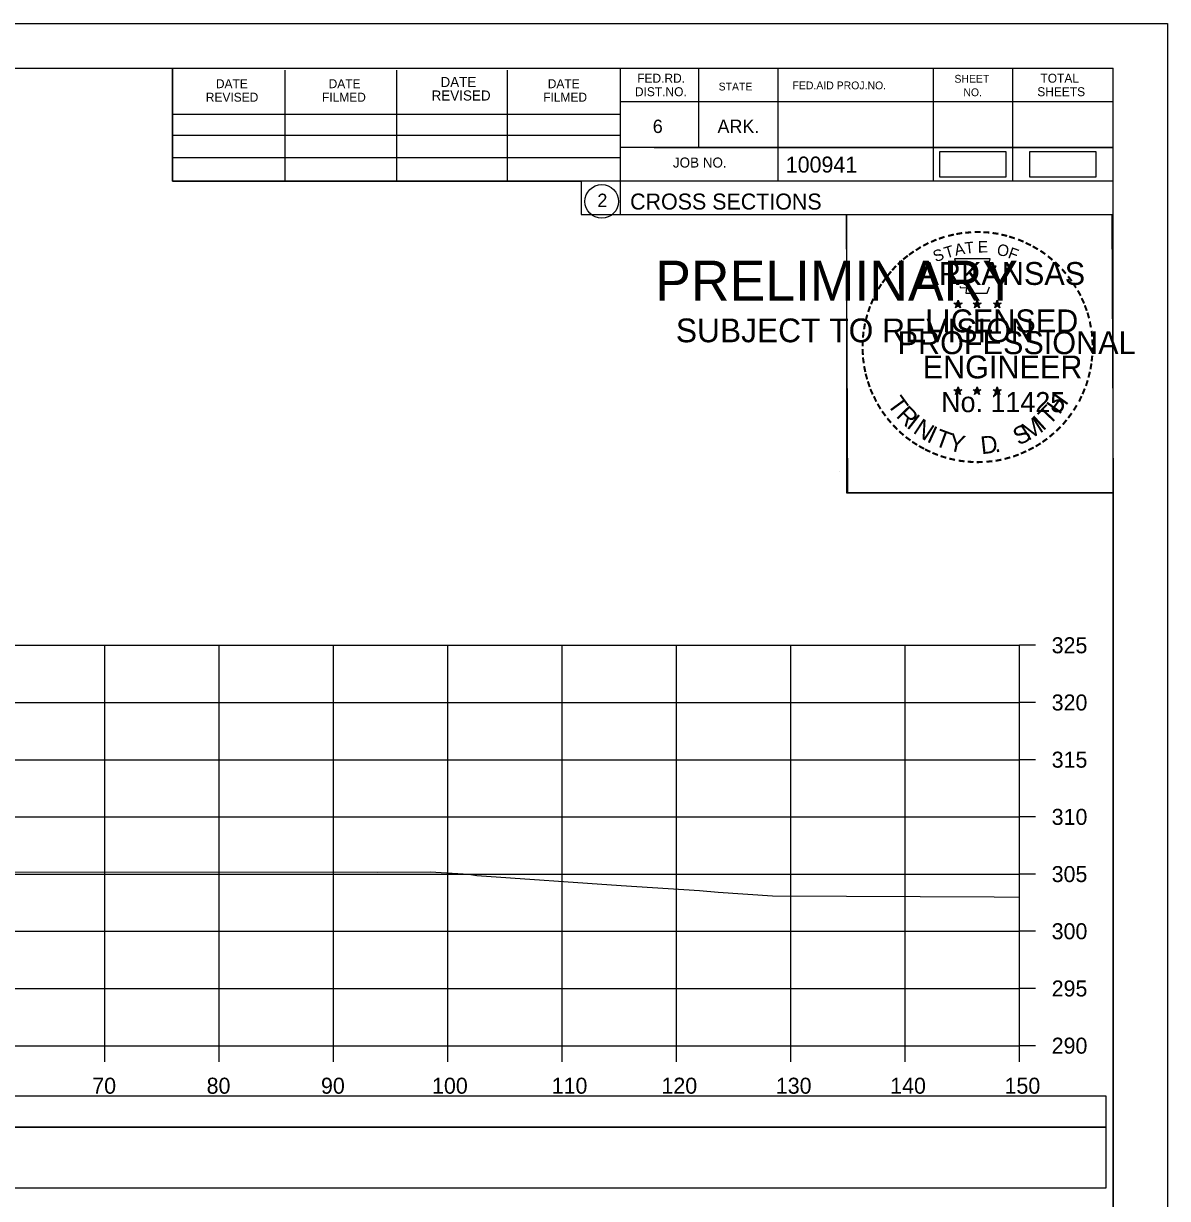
# Model space of a CAD drawing. Extents: x 1370538 to 1372872, y 376220 to 381127.
# Drawn here: x 1372771.5 to 1372871.6, y 378159.8 to 378262.5 of the extents above; entities that cross this region are included whole.
import ezdxf

# ---------------------------------------------------------------- set-up
doc = ezdxf.new("R2010")
doc.units = 0
for name, color, linetype in [('Default', 7, 'Continuous'), ('R_Border Notes', 7, 'Continuous'), ('R_Border PE', 7, 'Continuous'), ('R_Border Prem', 7, 'Continuous'), ('R_Dimension', 7, 'Continuous'), ('R_Grid', 7, 'Continuous'), ('R_Horz Alg Annot', 7, 'Continuous'), ('R_No Plot', 7, 'Continuous'), ('T_Indications', 7, 'Continuous'), ('T_Notes', 7, 'Continuous')]:
    doc.layers.add(name, color=color, linetype=linetype)

msp = doc.modelspace()

# ---------------------------------------------------------------- linework, layer by layer
at = {"layer": 'Default'}
for points in [[(1372851.64, 378249.15), (1372857.47, 378249.15), (1372857.47, 378251.33), (1372851.64, 378251.33)], [(1372859.51, 378249.15), (1372865.34, 378249.15), (1372865.34, 378251.33), (1372859.51, 378251.33)]]:
    msp.add_lwpolyline(points, close=True, dxfattribs=at)
at = {"layer": 'R_Border Notes'}
for p, q in [((1372550.65, 378258.65), (1372866.83, 378258.65)), ((1372784.57, 378248.77), (1372784.57, 378258.65)), ((1372794.43, 378248.77), (1372794.43, 378258.45)), ((1372804.19, 378248.77), (1372804.19, 378258.45)), ((1372813.87, 378248.77), (1372813.87, 378258.45)), ((1372823.73, 378258.65), (1372823.73, 378245.85)), ((1372830.57, 378258.65), (1372830.57, 378251.71)), ((1372837.51, 378258.65), (1372837.51, 378248.77)), ((1372851.09, 378258.65), (1372851.09, 378248.77)), ((1372858.03, 378258.65), (1372858.03, 378248.77)), ((1372866.83, 378053.19), (1372866.83, 378258.65)), ((1372866.83, 378255.71), (1372823.73, 378255.71)), ((1372866.83, 378255.73), (1372866.83, 378255.73)), ((1372784.57, 378254.63), (1372823.73, 378254.63)), ((1372784.57, 378252.77), (1372823.73, 378252.77)), ((1372866.83, 378251.71), (1372823.73, 378251.71)), ((1372826.69, 378251.71), (1372866.83, 378251.71)), ((1372784.57, 378248.77), (1372784.57, 378250.83)), ((1372784.57, 378250.83), (1372823.73, 378250.83)), ((1372866.83, 378248.77), (1372784.57, 378248.77)), ((1372823.73, 378245.85), (1372866.83, 378245.85))]:
    msp.add_line(p, q, dxfattribs=at)
msp.add_circle((1372822.11, 378246.99), 1.47, dxfattribs=at)
at = {"layer": 'R_Border Prem'}
for p, q in [((1372858.65, 378173.19), (1372858.65, 378208.19)), ((1372860.05, 378208.19), (1372858.65, 378208.19)), ((1372860.05, 378203.19), (1372858.65, 378203.19)), ((1372860.05, 378198.19), (1372858.65, 378198.19)), ((1372860.05, 378193.19), (1372858.65, 378193.19)), ((1372860.05, 378188.19), (1372858.65, 378188.19)), ((1372860.05, 378183.19), (1372858.65, 378183.19)), ((1372860.05, 378178.19), (1372858.65, 378178.19)), ((1372558.65, 378173.19), (1372858.65, 378173.19)), ((1372778.65, 378171.79), (1372778.65, 378173.19)), ((1372788.65, 378171.79), (1372788.65, 378173.19)), ((1372798.65, 378171.79), (1372798.65, 378173.19)), ((1372808.65, 378171.79), (1372808.65, 378173.19)), ((1372818.65, 378171.79), (1372818.65, 378173.19)), ((1372828.65, 378171.79), (1372828.65, 378173.19)), ((1372838.65, 378171.79), (1372838.65, 378173.19)), ((1372848.65, 378171.79), (1372848.65, 378173.19)), ((1372858.65, 378171.79), (1372858.65, 378173.19)), ((1372860.05, 378173.19), (1372858.65, 378173.19))]:
    msp.add_line(p, q, dxfattribs=at)
at = {"layer": 'R_Dimension'}
msp.add_lwpolyline([(1372755.15, 378188.38), (1372802.54, 378188.37), (1372807.11, 378188.4), (1372810.49, 378188.17), (1372811.19, 378188.07), (1372823.8, 378187.2), (1372830.66, 378186.74), (1372832.3, 378186.6), (1372837.04, 378186.3), (1372856.43, 378186.2), (1372858.65, 378186.18)], dxfattribs=at)
at = {"layer": 'R_Grid'}
for p, q in [((1372558.65, 378208.19), (1372858.65, 378208.19)), ((1372778.65, 378173.19), (1372778.65, 378208.19)), ((1372788.65, 378173.19), (1372788.65, 378208.19)), ((1372798.65, 378173.19), (1372798.65, 378208.19)), ((1372808.65, 378173.19), (1372808.65, 378208.19)), ((1372818.65, 378173.19), (1372818.65, 378208.19)), ((1372828.65, 378173.19), (1372828.65, 378208.19)), ((1372838.65, 378173.19), (1372838.65, 378208.19)), ((1372848.65, 378173.19), (1372848.65, 378208.19)), ((1372858.65, 378173.19), (1372858.65, 378208.19)), ((1372558.65, 378203.19), (1372858.65, 378203.19)), ((1372558.65, 378198.19), (1372858.65, 378198.19)), ((1372558.65, 378193.19), (1372858.65, 378193.19)), ((1372558.65, 378188.19), (1372858.65, 378188.19)), ((1372558.65, 378183.19), (1372858.65, 378183.19)), ((1372558.65, 378178.19), (1372858.65, 378178.19)), ((1372558.65, 378173.19), (1372858.65, 378173.19))]:
    msp.add_line(p, q, dxfattribs=at)
at = {"layer": 'R_Horz Alg Annot'}
for points in [[(1372551.09, 378166.07), (1372866.22, 378166.07), (1372866.22, 378168.78), (1372551.09, 378168.78)], [(1372551.09, 378160.75), (1372866.22, 378160.75), (1372866.22, 378166.07), (1372551.09, 378166.07)]]:
    msp.add_lwpolyline(points, close=True, dxfattribs=at)
at = {"layer": 'R_No Plot'}
for p, q in [((1372538.25, 378262.54), (1372871.58, 378262.54)), ((1372842.86, 378223.39), (1372842.86, 378223.39))]:
    msp.add_line(p, q, dxfattribs=at)
for points in [[(1372538.24, 378262.54), (1372871.58, 378262.54), (1372871.58, 378049.21), (1372538.24, 378049.21)], [(1372784.57, 378258.65), (1372784.57, 378248.77), (1372820.3, 378248.77), (1372820.3, 378245.85), (1372843.5, 378245.85), (1372843.5, 378221.52), (1372866.83, 378221.52), (1372866.83, 378053.19), (1372550.65, 378053.19), (1372550.65, 378258.65)], [(1372843.5, 378245.85), (1372866.71, 378245.85), (1372866.83, 378221.52), (1372843.62, 378221.52)]]:
    msp.add_lwpolyline(points, close=True, dxfattribs=at)
at = {"layer": 'T_Indications'}
for p, q in [((1372853.26, 378238.36), (1372853.22, 378238.11)), ((1372853.26, 378237.99), (1372853.26, 378238.36)), ((1372853.26, 378238.36), (1372853.31, 378238.11)), ((1372854.93, 378238.36), (1372854.89, 378238.11)), ((1372854.93, 378237.99), (1372854.93, 378238.36)), ((1372854.93, 378238.36), (1372854.98, 378238.11)), ((1372856.69, 378238.35), (1372856.65, 378238.09)), ((1372856.69, 378237.98), (1372856.69, 378238.35)), ((1372856.69, 378238.35), (1372856.74, 378238.1)), ((1372852.91, 378238.1), (1372853.26, 378237.99)), ((1372852.91, 378238.1), (1372853.16, 378238.06)), ((1372852.91, 378238.1), (1372853.15, 378237.98)), ((1372853.04, 378237.7), (1372853.26, 378237.99)), ((1372853.04, 378237.7), (1372853.17, 378237.94)), ((1372853.04, 378237.7), (1372853.26, 378237.91)), ((1372853.61, 378238.1), (1372853.26, 378237.99)), ((1372853.47, 378237.7), (1372853.26, 378237.99)), ((1372853.47, 378237.7), (1372853.26, 378237.91)), ((1372853.61, 378238.1), (1372853.32, 378238.06)), ((1372853.47, 378237.7), (1372853.34, 378237.99)), ((1372853.61, 378238.1), (1372853.4, 378238)), ((1372854.58, 378238.1), (1372854.93, 378237.99)), ((1372854.58, 378238.1), (1372854.83, 378238.06)), ((1372854.58, 378238.1), (1372854.82, 378237.98)), ((1372854.71, 378237.7), (1372854.93, 378237.99)), ((1372854.71, 378237.7), (1372854.84, 378237.94)), ((1372854.71, 378237.7), (1372854.93, 378237.91)), ((1372855.28, 378238.1), (1372854.93, 378237.99)), ((1372855.14, 378237.7), (1372854.93, 378237.99)), ((1372855.14, 378237.7), (1372854.93, 378237.91)), ((1372855.28, 378238.1), (1372854.99, 378238.06)), ((1372855.14, 378237.7), (1372855.01, 378237.99)), ((1372855.28, 378238.1), (1372855.07, 378238)), ((1372856.35, 378238.09), (1372856.69, 378237.98)), ((1372856.35, 378238.09), (1372856.6, 378238.05)), ((1372856.35, 378238.09), (1372856.58, 378237.97)), ((1372856.48, 378237.68), (1372856.69, 378237.98)), ((1372856.48, 378237.68), (1372856.6, 378237.93)), ((1372856.48, 378237.68), (1372856.69, 378237.9)), ((1372857.04, 378238.09), (1372856.69, 378237.98)), ((1372856.91, 378237.68), (1372856.69, 378237.98)), ((1372856.91, 378237.68), (1372856.69, 378237.9)), ((1372857.04, 378238.09), (1372856.76, 378238.04)), ((1372856.91, 378237.68), (1372856.77, 378237.98)), ((1372857.04, 378238.09), (1372856.84, 378237.99)), ((1372852.91, 378230.53), (1372853.26, 378230.42)), ((1372852.91, 378230.53), (1372853.16, 378230.49)), ((1372852.91, 378230.53), (1372853.14, 378230.41)), ((1372853.04, 378230.12), (1372853.26, 378230.42)), ((1372853.04, 378230.12), (1372853.17, 378230.37)), ((1372853.04, 378230.12), (1372853.25, 378230.34)), ((1372853.26, 378230.79), (1372853.22, 378230.53)), ((1372853.47, 378230.12), (1372853.25, 378230.34)), ((1372853.26, 378230.42), (1372853.26, 378230.79)), ((1372853.26, 378230.79), (1372853.31, 378230.54)), ((1372853.6, 378230.53), (1372853.26, 378230.42)), ((1372853.47, 378230.12), (1372853.26, 378230.42)), ((1372853.6, 378230.53), (1372853.32, 378230.48)), ((1372853.47, 378230.12), (1372853.33, 378230.41)), ((1372853.6, 378230.53), (1372853.4, 378230.43)), ((1372854.58, 378230.53), (1372854.93, 378230.42)), ((1372854.58, 378230.53), (1372854.83, 378230.49)), ((1372854.58, 378230.53), (1372854.81, 378230.41)), ((1372854.71, 378230.12), (1372854.93, 378230.42)), ((1372854.71, 378230.12), (1372854.84, 378230.37)), ((1372854.71, 378230.12), (1372854.92, 378230.34)), ((1372854.93, 378230.79), (1372854.88, 378230.53)), ((1372855.14, 378230.12), (1372854.92, 378230.34)), ((1372854.93, 378230.42), (1372854.93, 378230.79)), ((1372854.93, 378230.79), (1372854.97, 378230.54)), ((1372855.27, 378230.53), (1372854.93, 378230.42)), ((1372855.14, 378230.12), (1372854.93, 378230.42)), ((1372855.27, 378230.53), (1372854.99, 378230.48)), ((1372855.14, 378230.12), (1372855, 378230.41)), ((1372855.27, 378230.53), (1372855.07, 378230.43)), ((1372856.34, 378230.52), (1372856.69, 378230.41)), ((1372856.34, 378230.52), (1372856.6, 378230.48)), ((1372856.34, 378230.52), (1372856.58, 378230.4)), ((1372856.48, 378230.11), (1372856.69, 378230.41)), ((1372856.48, 378230.11), (1372856.6, 378230.36)), ((1372856.48, 378230.11), (1372856.69, 378230.33)), ((1372856.69, 378230.78), (1372856.65, 378230.52)), ((1372856.69, 378230.41), (1372856.69, 378230.78)), ((1372856.69, 378230.78), (1372856.74, 378230.53)), ((1372857.04, 378230.52), (1372856.69, 378230.41)), ((1372856.91, 378230.11), (1372856.69, 378230.41)), ((1372856.91, 378230.11), (1372856.69, 378230.33)), ((1372857.04, 378230.52), (1372856.75, 378230.47)), ((1372856.91, 378230.11), (1372856.77, 378230.4)), ((1372857.04, 378230.52), (1372856.84, 378230.42))]:
    msp.add_line(p, q, dxfattribs=at)
for points in [[(1372852.95, 378241.98), (1372853.22, 378241.16)], [(1372856.46, 378241.06), (1372856.61, 378241.34), (1372855.92, 378241.32), (1372856.07, 378241.98), (1372852.95, 378241.98)], [(1372853.44, 378239.56), (1372853.44, 378239.47), (1372854.01, 378239.45), (1372853.95, 378238.98), (1372855.82, 378238.98), (1372856.02, 378239.52)], [(1372853.26, 378238.36), (1372853.47, 378237.7), (1372852.91, 378238.1), (1372853.61, 378238.1), (1372853.04, 378237.7), (1372853.26, 378238.36)], [(1372854.93, 378238.36), (1372855.14, 378237.7), (1372854.58, 378238.1), (1372855.28, 378238.1), (1372854.71, 378237.7), (1372854.93, 378238.36)], [(1372856.69, 378238.35), (1372856.91, 378237.68), (1372856.35, 378238.09), (1372857.04, 378238.09), (1372856.48, 378237.68), (1372856.69, 378238.35)], [(1372853.26, 378230.79), (1372853.47, 378230.12), (1372852.91, 378230.53), (1372853.6, 378230.53), (1372853.04, 378230.12), (1372853.26, 378230.79)], [(1372854.93, 378230.79), (1372855.14, 378230.12), (1372854.58, 378230.53), (1372855.27, 378230.53), (1372854.71, 378230.12), (1372854.93, 378230.79)], [(1372856.69, 378230.78), (1372856.91, 378230.11), (1372856.34, 378230.52), (1372857.04, 378230.52), (1372856.48, 378230.11), (1372856.69, 378230.78)]]:
    msp.add_lwpolyline(points, dxfattribs=at)
for centre, radius in [((1372853.26, 378237.99), 0.172), ((1372853.26, 378237.99), 0.145), ((1372853.26, 378237.99), 0.116), ((1372853.26, 378237.99), 0.0991), ((1372853.26, 378237.99), 0.0747), ((1372853.26, 378237.99), 0.0495), ((1372853.26, 378237.99), 0.0296), ((1372854.93, 378237.99), 0.172), ((1372854.93, 378237.99), 0.145), ((1372854.93, 378237.99), 0.116), ((1372854.93, 378237.99), 0.0991), ((1372854.93, 378237.99), 0.0747), ((1372854.93, 378237.99), 0.0495), ((1372854.93, 378237.99), 0.0296), ((1372856.69, 378237.98), 0.172), ((1372856.69, 378237.98), 0.145), ((1372856.69, 378237.98), 0.116), ((1372856.69, 378237.98), 0.0991), ((1372856.69, 378237.98), 0.0747), ((1372856.69, 378237.98), 0.0495), ((1372856.69, 378237.98), 0.0296), ((1372853.26, 378230.42), 0.172), ((1372853.26, 378230.42), 0.145), ((1372853.26, 378230.42), 0.116), ((1372853.26, 378230.42), 0.0991), ((1372853.26, 378230.42), 0.0747), ((1372853.26, 378230.42), 0.0495), ((1372853.26, 378230.42), 0.0296), ((1372854.92, 378230.42), 0.172), ((1372854.92, 378230.42), 0.145), ((1372854.92, 378230.42), 0.116), ((1372854.92, 378230.42), 0.0991), ((1372854.92, 378230.42), 0.0747), ((1372854.92, 378230.42), 0.0495), ((1372854.92, 378230.42), 0.0296), ((1372856.69, 378230.41), 0.172), ((1372856.69, 378230.41), 0.145), ((1372856.69, 378230.41), 0.116), ((1372856.69, 378230.41), 0.0991), ((1372856.69, 378230.41), 0.0747), ((1372856.69, 378230.41), 0.0495), ((1372856.69, 378230.41), 0.0296)]:
    msp.add_circle(centre, radius, dxfattribs=at)

# ---------------------------------------------------------------- texts
at = {"layer": 'R_Border Notes'}
for s, height, p in [('DATE', 0.879, (1372808.01, 378256.99)), ('FED.RD.', 0.782, (1372825.21, 378257.37)), ('SHEET', 0.684, (1372852.95, 378257.37)), ('TOTAL', 0.782, (1372860.47, 378257.37)), ('DATE', 0.782, (1372788.37, 378256.89)), ('DATE', 0.782, (1372798.23, 378256.89)), ('DATE', 0.782, (1372817.39, 378256.89)), ('DIST.NO.', 0.782, (1372825.01, 378256.19)), ('STATE', 0.684, (1372832.33, 378256.69)), ('FED.AID PROJ.NO.', 0.684, (1372838.79, 378256.79)), ('NO.', 0.684, (1372853.73, 378256.19)), ('SHEETS', 0.782, (1372860.19, 378256.19)), ('REVISED', 0.782, (1372787.49, 378255.71)), ('FILMED', 0.782, (1372797.65, 378255.71)), ('REVISED', 0.879, (1372807.23, 378255.81)), ('FILMED', 0.782, (1372816.99, 378255.71)), ('6', 1.17, (1372826.57, 378252.97)), ('ARK.', 1.172, (1372832.23, 378252.97)), ('JOB NO.', 0.879, (1372828.33, 378249.95)), ('100941', 1.4, (1372838.2, 378249.51)), ('2', 1.17, (1372821.73, 378246.5)), ('CROSS SECTIONS', 1.4, (1372824.59, 378246.28))]:
    msp.add_text(s, height=height, rotation=360, dxfattribs=at).set_placement(p)
at = {"layer": 'R_Border PE'}
for s, p in [('325', (1372861.45, 378207.49)), ('320', (1372861.45, 378202.49)), ('315', (1372861.45, 378197.49)), ('310', (1372861.45, 378192.49)), ('305', (1372861.45, 378187.49)), ('300', (1372861.45, 378182.49)), ('295', (1372861.45, 378177.49)), ('290', (1372861.45, 378172.49)), ('70', (1372777.56, 378168.99)), ('80', (1372787.56, 378168.99)), ('90', (1372797.56, 378168.99)), ('100', (1372807.27, 378168.99)), ('110', (1372817.73, 378168.99)), ('120', (1372827.33, 378168.99)), ('130', (1372837.33, 378168.99)), ('140', (1372847.33, 378168.99)), ('150', (1372857.33, 378168.99))]:
    msp.add_text(s, height=1.4, dxfattribs=at).set_placement(p)
at = {"layer": 'T_Indications'}
for s, height, rotation, p in [('-', 1.6, 24.3072, (1372851.07, 378242.84)), ('-', 1.6, 19.1761, (1372851.7, 378243.11)), ('-', 1.6, 13.6301, (1372852.45, 378243.35)), ('-', 1.6, 10.2193, (1372853.13, 378243.51)), ('T', 1, 6.0228, (1372853.9, 378242.41)), ('-', 1.6, 5.8968, (1372853.86, 378243.62)), ('-', 1.6, 0.1862, (1372854.63, 378243.69)), ('E', 1, 0.8323, (1372855, 378242.52)), ('-', 1.6, 357.743, (1372855.35, 378243.68)), ('-', 1.6, 352.1617, (1372856.1, 378243.63)), ('-', 1.6, 347.2049, (1372856.82, 378243.51)), ('-', 1.6, 342.3362, (1372857.45, 378243.36)), ('-', 1.6, 337.8551, (1372858.19, 378243.13)), ('-', 1.6, 36.2317, (1372849.26, 378241.76)), ('-', 1.6, 34.0636, (1372849.84, 378242.15)), ('-', 1.6, 28.7918, (1372850.43, 378242.52)), ('S', 1, 21.594, (1372851.31, 378241.66)), ('T', 1, 16.4036, (1372852.22, 378241.99)), ('A', 1, 11.2132, (1372853.05, 378242.24)), ('O', 1, 350.4515, (1372856.61, 378242.31)), ('F', 1, 340.0707, (1372857.56, 378242.08)), ('-', 1.6, 334.1211, (1372858.82, 378242.86)), ('-', 1.6, 329.6409, (1372859.4, 378242.58)), ('-', 1.6, 325.8627, (1372860.04, 378242.22)), ('-', 1.6, 42.9622, (1372848.35, 378240.96)), ('-', 1.6, 38.9507, (1372848.78, 378241.38)), ('ARKANSAS', 2, 360, (1372849.81, 378239.69)), ('-', 1.6, 320.5297, (1372860.65, 378241.79)), ('-', 1.6, 315.5786, (1372861.25, 378241.3)), ('-', 1.6, 50.6142, (1372847.5, 378240)), ('-', 1.6, 48.423, (1372847.9, 378240.49)), ('-', 1.6, 309.8797, (1372861.82, 378240.75)), ('-', 1.6, 306.6522, (1372862.34, 378240.15)), ('-', 1.6, 58.0706, (1372846.76, 378238.91)), ('-', 1.6, 54.2325, (1372847.09, 378239.43)), ('-', 1.4, 303.6753, (1372862.83, 378239.58)), ('-', 1.6, 67.7743, (1372846.19, 378237.68)), ('-', 1.6, 62.8713, (1372846.45, 378238.29)), ('-', 1.6, 299.6684, (1372863.15, 378238.98)), ('-', 1.6, 294.6628, (1372863.47, 378238.37)), ('-', 1.6, 72.3945, (1372845.97, 378237.05)), ('LICENSED', 2, 360, (1372850.4, 378235.55)), ('DWB', 0.01, 360, (1372853.25, 378237.99)), ('DWB', 0.01, 360, (1372854.92, 378237.99)), ('DWB', 0.01, 360, (1372856.68, 378237.98)), ('-', 1.6, 290.5728, (1372863.73, 378237.79)), ('-', 1.6, 81.2013, (1372845.64, 378235.62)), ('-', 1.6, 75.461, (1372845.77, 378236.34)), ('-', 1.6, 285.1233, (1372863.96, 378237.21)), ('-', 1.6, 280.5493, (1372864.16, 378236.47)), ('-', 1.6, 85.1863, (1372845.56, 378234.93)), ('PROFESSIONAL', 2, 360, (1372847.98, 378233.64)), ('-', 1.6, 276.5962, (1372864.32, 378235.7)), ('-', 1.6, 89.0622, (1372845.54, 378234.23)), ('-', 1.6, 274.3301, (1372864.38, 378234.98)), ('-', 1.6, 269.9407, (1372864.42, 378234.34)), ('-', 1.6, 94.1959, (1372845.57, 378233.51)), ('-', 1.6, 98.9479, (1372845.65, 378232.84)), ('ENGINEER', 2, 360, (1372850.17, 378231.52)), ('-', 1.6, 263.5172, (1372864.4, 378233.68)), ('-', 1.6, 101.7149, (1372845.78, 378232.11)), ('-', 1.6, 260.9953, (1372864.33, 378233.02)), ('-', 1.6, 105.4578, (1372845.94, 378231.51)), ('-', 1.6, 109.0874, (1372846.16, 378230.88)), ('-', 1.6, 252.8681, (1372864.04, 378231.63)), ('-', 1.6, 255.7626, (1372864.22, 378232.35)), ('-', 1.6, 114.0643, (1372846.41, 378230.28)), ('T', 1.54, 306.0406, (1372847.02, 378229.26)), ('No. 11425', 1.757, 360, (1372851.79, 378228.57)), ('DWB', 0.01, 360, (1372853.24, 378230.42)), ('DWB', 0.01, 360, (1372854.91, 378230.42)), ('DWB', 0.01, 360, (1372856.68, 378230.41)), ('H', 1.54, 54.6088, (1372862.14, 378228.29)), ('-', 1.6, 247.8887, (1372863.81, 378230.95)), ('-', 1.6, 115.7289, (1372846.72, 378229.67)), ('-', 1.6, 120.4471, (1372847.07, 378229.08)), ('R', 1.54, 314.005, (1372847.78, 378228.21)), ('T', 1.54, 46.6444, (1372861.25, 378227.35)), ('-', 1.6, 239.0712, (1372863.16, 378229.57)), ('-', 1.6, 244.6197, (1372863.55, 378230.32)), ('-', 1.6, 125.8934, (1372847.48, 378228.52)), ('-', 1.6, 130.7181, (1372847.94, 378227.97)), ('I', 1.54, 321.9694, (1372848.68, 378227.28)), ('M', 1.54, 32.6563, (1372859.4, 378226.03)), ('I', 1.54, 42.1136, (1372860.68, 378226.87)), ('-', 1.6, 233.8452, (1372862.76, 378228.92)), ('-', 1.6, 134.2238, (1372848.46, 378227.42)), ('N', 1.54, 326.5002, (1372849.25, 378226.81)), ('I', 1.54, 335.3603, (1372850.45, 378226.02)), ('T', 1.54, 339.8912, (1372851.12, 378225.69)), ('S', 1.54, 26.9312, (1372858.56, 378225.62)), ('-', 1.6, 225.7653, (1372861.85, 378227.79)), ('-', 1.6, 231.2538, (1372862.33, 378228.35)), ('-', 1.6, 138.9338, (1372848.98, 378226.96)), ('-', 1.6, 144.6463, (1372849.54, 378226.55)), ('-', 1.6, 148.0898, (1372850.1, 378226.18)), ('Y', 1.54, 347.8556, (1372852.33, 378225.25)), ('D', 1.54, 6.3969, (1372855.32, 378224.89)), ('-', 1.6, 215.7363, (1372860.78, 378226.81)), ('-', 1.6, 221.0851, (1372861.32, 378227.28)), ('-', 1.6, 151.5704, (1372850.68, 378225.86)), ('-', 1.6, 154.6002, (1372851.2, 378225.61)), ('-', 1.6, 158.5612, (1372851.82, 378225.36)), ('.', 1.54, 13.7642, (1372856.51, 378225.02)), ('-', 1.6, 204.2516, (1372859.06, 378225.76)), ('-', 1.6, 207.3568, (1372859.68, 378226.08)), ('-', 1.6, 212.2491, (1372860.24, 378226.42)), ('-', 1.6, 162.7983, (1372852.51, 378225.14)), ('-', 1.6, 167.5555, (1372853.23, 378224.98)), ('-', 1.6, 173.1155, (1372854, 378224.87)), ('-', 1.6, 176.5183, (1372854.75, 378224.82)), ('-', 1.6, 181.5918, (1372855.49, 378224.83)), ('-', 1.6, 185.8167, (1372856.3, 378224.91)), ('-', 1.6, 191.2858, (1372857.03, 378225.04)), ('-', 1.6, 195.4743, (1372857.76, 378225.24)), ('-', 1.6, 200.7184, (1372858.44, 378225.48))]:
    msp.add_text(s, height=height, rotation=rotation, dxfattribs=at).set_placement(p)
at = {"layer": 'T_Notes'}
for s, height, p in [('PRELIMINARY', 3.5, (1372826.78, 378238.31)), ('DWB', 0.01, (1372827.52, 378240.16)), ('SUBJECT TO REVISION', 2.0751, (1372828.59, 378234.68))]:
    msp.add_text(s, height=height, rotation=360, dxfattribs=at).set_placement(p)

doc.saveas('drawing.dxf')
